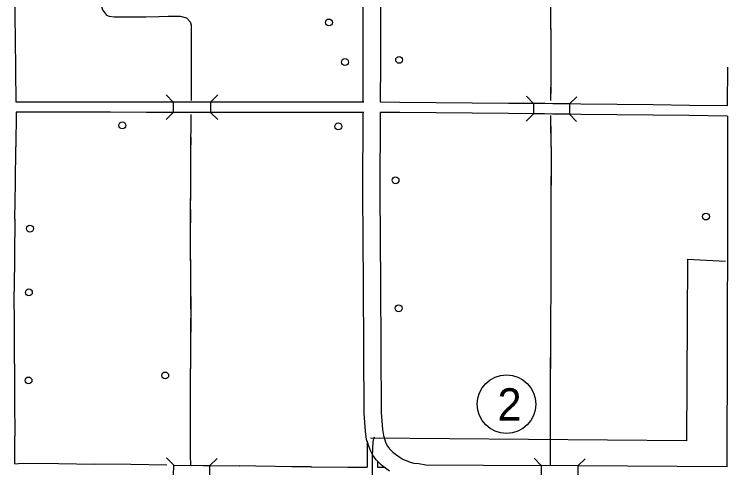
# Model space of a CAD drawing. Extents: x -4306 to 3843, y 131 to 8053.
# Drawn here: x -1917 to -251, y 3654 to 4712 of the extents above; entities that cross this region are included whole.
import ezdxf

# ---------------------------------------------------------------- set-up
doc = ezdxf.new("R2010")
doc.units = 0
for name, color, linetype in [('10', 7, 'Continuous'), ('31', 7, 'Continuous'), ('32', 7, 'Continuous'), ('33', 7, 'Continuous'), ('37', 7, 'Continuous'), ('38', 7, 'Continuous'), ('43', 7, 'Continuous'), ('56', 7, 'Continuous'), ('6', 7, 'Continuous'), ('R_No Plot', 7, 'Continuous')]:
    doc.layers.add(name, color=color, linetype=linetype)

msp = doc.modelspace()

# ---------------------------------------------------------------- linework, layer by layer
at = {"layer": '10'}
for p, q in [((-1100.3, 3780.5), (-1101.9, 4080.9)), ((-1096.8, 3739), (-1100.3, 3780.5)), ((-1094.3, 3719.7), (-1096.8, 3739)), ((-1086.2, 3695.3), (-1094.3, 3719.7)), ((-1079.5, 3682.8), (-1086.2, 3695.3)), ((-1071.8, 3672), (-1079.5, 3682.8)), ((-1059.8, 3659.7), (-1071.8, 3672)), ((-1040.8, 3645.6), (-1059.8, 3659.7)), ((-686.3, 3658.5), (-686.6, 3618.5)), ((-601.1, 3657.9), (-686.2, 3658.5)), ((-600.7, 3657.9), (-601, 3617.9)), ((-252.8, 3655.5), (-600.7, 3657.9))]:
    msp.add_line(p, q, dxfattribs=at)
for points in [[(-1102.4, 4507.2), (-1102, 4600.1), (-1102.8, 4916.5), (-1106.4, 5331), (-1107.8, 5367)], [(-1067.7, 5365.9), (-1066.4, 5331.9), (-1062.8, 4916.7), (-1062, 4600.1), (-1062.4, 4507.1)], [(-1101.9, 4080.9), (-1103.3, 4295.8), (-1102.5, 4483.2)], [(-1062.5, 4483.1), (-1063.3, 4295.8), (-1061.9, 4081.1)], [(-1061.9, 4081.1), (-1060.3, 3782.3), (-1057, 3743.3), (-1055.1, 3728.7), (-1049.3, 3711.2), (-1045.5, 3704), (-1041, 3697.8), (-1033.3, 3689.9), (-1018.4, 3678.8), (-1009.5, 3673.4), (-992.3, 3666.7), (-984.1, 3664.3), (-972.2, 3663.4), (-956, 3660.3), (-686.3, 3658.5)]]:
    msp.add_lwpolyline(points, dxfattribs=at)
at = {"layer": '31'}
for p, q in [((-1912.7, 4483.5), (-1913.6, 4402.7)), ((-251.3, 4474.7), (-251.4, 4402.1)), ((-1913.6, 4402.7), (-1913.6, 4402.7)), ((-251.4, 4402.1), (-251.6, 4317.6)), ((-1915.4, 4233.8), (-1916.2, 4149.3)), ((-1916.2, 4149.3), (-1917.1, 4070.3)), ((-1917.1, 4070.3), (-1917.1, 4065)), ((-1916.5, 3896), (-1916.3, 3811.5)), ((-1916.3, 3811.5), (-1916, 3727)), ((-1916, 3727), (-1916, 3727)), ((-1915.8, 3662.9), (-1898.4, 3664.6)), ((-1898.4, 3664.6), (-1813.9, 3663.4)), ((-1813.9, 3663.4), (-1729.4, 3662.3)), ((-1545.1, 3635.8), (-1544.8, 3659.8)), ((-1544.8, 3659.8), (-1476, 3658.9)), ((-1476, 3658.9), (-1460.2, 3658.7)), ((-1460.5, 3634.7), (-1460.2, 3658.7)), ((-1460.1, 3658.8), (-1391.5, 3657.8)), ((-1222.6, 3655.8), (-1138.1, 3655.3)), ((-1138.1, 3655.3), (-1093, 3654.9)), ((-1069, 3654.8), (-1053, 3654.7))]:
    msp.add_line(p, q, dxfattribs=at)
for points in [[(-1914.5, 4656.5), (-1915.1, 4704.7), (-1915.3, 4740.9)], [(-1912.8, 4507.5), (-1914.5, 4656.5)], [(-251.2, 4498.7), (-250.5, 4588.7)], [(-1914.5, 4318.3), (-1913.6, 4402.7)], [(-1915.4, 4233.8), (-1914.5, 4318.3)], [(-251.6, 4317.6), (-251.7, 4233.1)], [(-251.7, 4233.1), (-252.8, 3655.5)], [(-1916.8, 3980.5), (-1917.1, 4065)], [(-1916.5, 3896), (-1916.8, 3980.5)], [(-1915.8, 3662.9), (-1916, 3727)], [(-1074.7, 3724.2), (-1078.5, 3721.7), (-1079.5, 3714.3), (-1081.3, 3682.4), (-1081.6, 3642.9), (-1081, 3429.9), (-1081.6, 3132.7)], [(-1644.9, 3661.2), (-1729.4, 3662.3)], [(-1560.5, 3660), (-1644.9, 3661.2)], [(-1307, 3656.6), (-1353.3, 3657.3), (-1391.5, 3657.8)], [(-1222.6, 3655.8), (-1268.8, 3656.1), (-1307, 3656.6)]]:
    msp.add_lwpolyline(points, dxfattribs=at)
at = {"layer": '32'}
for p, q in [((-1861.3, 4507.5), (-1912.8, 4507.5)), ((-1776.8, 4507.5), (-1861.3, 4507.5)), ((-1692.4, 4507.5), (-1776.8, 4507.5)), ((-1607.9, 4507.4), (-1692.4, 4507.5)), ((-1545.7, 4507.4), (-1607.9, 4507.4)), ((-1545.7, 4507.4), (-1545.7, 4483.4)), ((-1523.4, 4507.4), (-1545.7, 4507.4)), ((-1459, 4507.4), (-1523.4, 4507.4)), ((-1459, 4507.4), (-1459, 4483.4)), ((-1438.9, 4507.4), (-1459, 4507.4)), ((-1354.4, 4507.3), (-1438.9, 4507.4)), ((-1269.9, 4507.3), (-1354.4, 4507.3)), ((-1185.4, 4507.3), (-1269.9, 4507.3)), ((-1100.9, 4507.2), (-1185.4, 4507.3)), ((-1016.3, 4506.7), (-1062.4, 4507.1)), ((-931.9, 4505.9), (-1016.3, 4506.7)), ((-847.4, 4505.2), (-931.9, 4505.9)), ((-762.9, 4504.4), (-847.4, 4505.2)), ((-704.4, 4503.9), (-762.9, 4504.4)), ((-704.4, 4504.1), (-704.7, 4480.1)), ((-678.4, 4503.7), (-704.4, 4503.9)), ((-659.7, 4503.5), (-678.4, 4503.7)), ((-620.5, 4503.1), (-659.7, 4503.5)), ((-620.5, 4503.1), (-620.7, 4479.1)), ((-593.9, 4502.7), (-620.5, 4503.1)), ((-509.4, 4501.7), (-593.9, 4502.7)), ((-424.9, 4500.7), (-509.4, 4501.7)), ((-340.4, 4499.7), (-424.9, 4500.7)), ((-251.2, 4498.7), (-340.4, 4499.7)), ((-1861.3, 4483.5), (-1912.7, 4483.5)), ((-1776.9, 4483.5), (-1861.3, 4483.5)), ((-1692.4, 4483.5), (-1776.9, 4483.5)), ((-1607.9, 4483.4), (-1692.4, 4483.5)), ((-1545.7, 4483.4), (-1607.9, 4483.4)), ((-1523.4, 4483.4), (-1545.7, 4483.4)), ((-1459, 4483.4), (-1523.4, 4483.4)), ((-1438.9, 4483.4), (-1459, 4483.4)), ((-1354.4, 4483.3), (-1438.9, 4483.4)), ((-1269.9, 4483.3), (-1354.4, 4483.3)), ((-1185.4, 4483.3), (-1269.9, 4483.3)), ((-1100.9, 4483.2), (-1185.4, 4483.3)), ((-1016.6, 4482.7), (-1062.5, 4483.1)), ((-932.1, 4481.9), (-1016.6, 4482.7)), ((-847.6, 4481.2), (-932.1, 4481.9)), ((-763.1, 4480.4), (-847.6, 4481.2)), ((-704.7, 4479.9), (-763.1, 4480.4)), ((-678.6, 4479.7), (-704.7, 4479.9)), ((-660, 4479.5), (-678.6, 4479.7)), ((-620.7, 4479.1), (-660, 4479.5)), ((-594.2, 4478.7), (-620.7, 4479.1)), ((-509.7, 4477.7), (-594.2, 4478.7)), ((-425.2, 4476.7), (-509.7, 4477.7)), ((-340.7, 4475.7), (-425.2, 4476.7)), ((-251.3, 4474.7), (-340.7, 4475.7))]:
    msp.add_line(p, q, dxfattribs=at)
at = {"layer": '33'}
for p, q in [((-1092.9, 3715.7), (-1093, 3654.9)), ((-1069, 3668.1), (-1069, 3654.8))]:
    msp.add_line(p, q, dxfattribs=at)
at = {"layer": '37'}
for points in [[(-686.3, 3658.5), (-703.2, 3675.6)], [(-584, 3674.7), (-601.1, 3657.9)]]:
    msp.add_lwpolyline(points, dxfattribs=at)
at = {"layer": '38'}
for points in [[(-1562.6, 4524.4), (-1545.7, 4507.4)], [(-1459, 4507.4), (-1442, 4524.3)], [(-721.2, 4521.1), (-704.4, 4503.9)], [(-620.5, 4503.1), (-603.3, 4519.8)], [(-1545.7, 4483.4), (-1562.7, 4466.4)], [(-1442, 4466.4), (-1459, 4483.4)], [(-704.7, 4479.9), (-721.8, 4463.1)], [(-603.9, 4461.9), (-620.7, 4479.1)], [(-1561.4, 3677), (-1544.7, 3659.8)], [(-1460.2, 3658.7), (-1443, 3675.4)]]:
    msp.add_lwpolyline(points, dxfattribs=at)
at = {"layer": '43'}
for points in [[(-664, 4510.8), (-663.1, 4574.9), (-664.4, 4780.1), (-664.5, 4897), (-663.2, 5181.9), (-666.9, 5268.2), (-668.6, 5276.5), (-676.6, 5316), (-684.7, 5352.5)], [(-1721.6, 5121), (-1719.2, 4906.7), (-1720.1, 4784.8), (-1716.6, 4741.4), (-1710.8, 4722.6), (-1701.9, 4710.3), (-1695.8, 4707.8), (-1684.1, 4706.1), (-1629, 4706.2), (-1529.5, 4708.1), (-1515.1, 4704), (-1506, 4694.6), (-1503.6, 4686.6), (-1504.1, 4607.4), (-1504.2, 4510.8)], [(-1713.4, 4730.9), (-1710.8, 4722.6), (-1701.9, 4710.3), (-1695.8, 4707.8), (-1684.1, 4706.1), (-1663, 4706.1)], [(-1641.9, 4706.2), (-1629, 4706.2), (-1610.2, 4706.6)], [(-1610.2, 4706.6), (-1578.5, 4707.2)], [(-1557.4, 4707.6), (-1529.5, 4708.1), (-1515.1, 4704), (-1506, 4694.6), (-1503.9, 4687.5)], [(-663.6, 4648.1), (-663.9, 4711.5)], [(-1503.7, 4666.4), (-1504.1, 4607.4), (-1504.1, 4603)], [(-663.2, 4563.6), (-663.1, 4574.9), (-663.4, 4627)], [(-1504.1, 4581.9), (-1504.2, 4518.5)], [(-664, 4510.8), (-663.5, 4542.5)], [(-1504.4, 4478.2), (-1505.2, 4388.9), (-1506, 4177.7), (-1505.1, 4012.5), (-1506.2, 3840.6), (-1506.1, 3682.7), (-1505.3, 3659.3)], [(-1504.4, 4478.2), (-1504.7, 4446.5)], [(-664.9, 3658.3), (-664.8, 3769), (-664.2, 3999.1), (-663.1, 4070.7), (-663.3, 4248.8), (-662.5, 4377), (-664.1, 4475.7)], [(-662.7, 4387), (-663.7, 4450.4)], [(-1504.9, 4425.4), (-1505.2, 4388.9), (-1505.3, 4362)], [(-662.9, 4302.5), (-662.6, 4365.9)], [(-1505.4, 4340.9), (-1505.7, 4277.5)], [(-663.2, 4218.1), (-663.3, 4248.8), (-663.1, 4281.4)], [(-1505.7, 4256.4), (-1506, 4193)], [(-663.2, 4165.2), (-663.2, 4196.9)], [(-1506, 4171.9), (-1505.6, 4108.6)], [(-663.1, 4133.6), (-663.2, 4165.2)], [(-663.4, 4049.1), (-663.1, 4070.7), (-663.1, 4112.4)], [(-1505.5, 4087.4), (-1505.2, 4024.1)], [(-664.3, 3964.6), (-664.2, 3999.1), (-663.7, 4028)], [(-1505.2, 4002.9), (-1505.4, 3971.3)], [(-1505.4, 3971.3), (-1505.6, 3939.6)], [(-664.5, 3880.1), (-664.3, 3943.5)], [(-1505.7, 3918.5), (-1506.1, 3855.1)], [(-664.7, 3795.6), (-664.5, 3859)], [(-1506.2, 3834), (-1506.2, 3770.6)], [(-664.8, 3711.1), (-664.8, 3769), (-664.8, 3774.5)], [(-1506.1, 3749.5), (-1506.1, 3686.1)], [(-664.9, 3658.3), (-664.9, 3690)]]:
    msp.add_lwpolyline(points, dxfattribs=at)
at = {"layer": '56'}
for centre in [(-1182.1, 4693.2), (-1144.9, 4600.9), (-1018.3, 4605.9), (-1664.6, 4453), (-1160.3, 4450.6), (-1026.7, 4324.7), (-301.8, 4240.1), (-1880.5, 4212), (-1882.9, 4063), (-1019.6, 4025.9), (-1564.6, 3869.1), (-1883.8, 3857.4)]:
    msp.add_circle(centre, 8, dxfattribs=at)
at = {"layer": '6'}
msp.add_line((-344.8, 4140.3), (-256.2, 4135.9), dxfattribs=at)
for points in [[(-344.8, 4140.3), (-347.2, 3716.3)], [(-347.2, 3716.3), (-1085.2, 3722.9)]]:
    msp.add_lwpolyline(points, dxfattribs=at)
at = {"layer": 'R_No Plot'}
msp.add_circle((-767.7, 3802.1), 68.6, dxfattribs=at)

# ---------------------------------------------------------------- texts
msp.add_text('2', height=75.7, dxfattribs=at).set_placement((-788.7, 3763.5))

doc.saveas('drawing.dxf')
